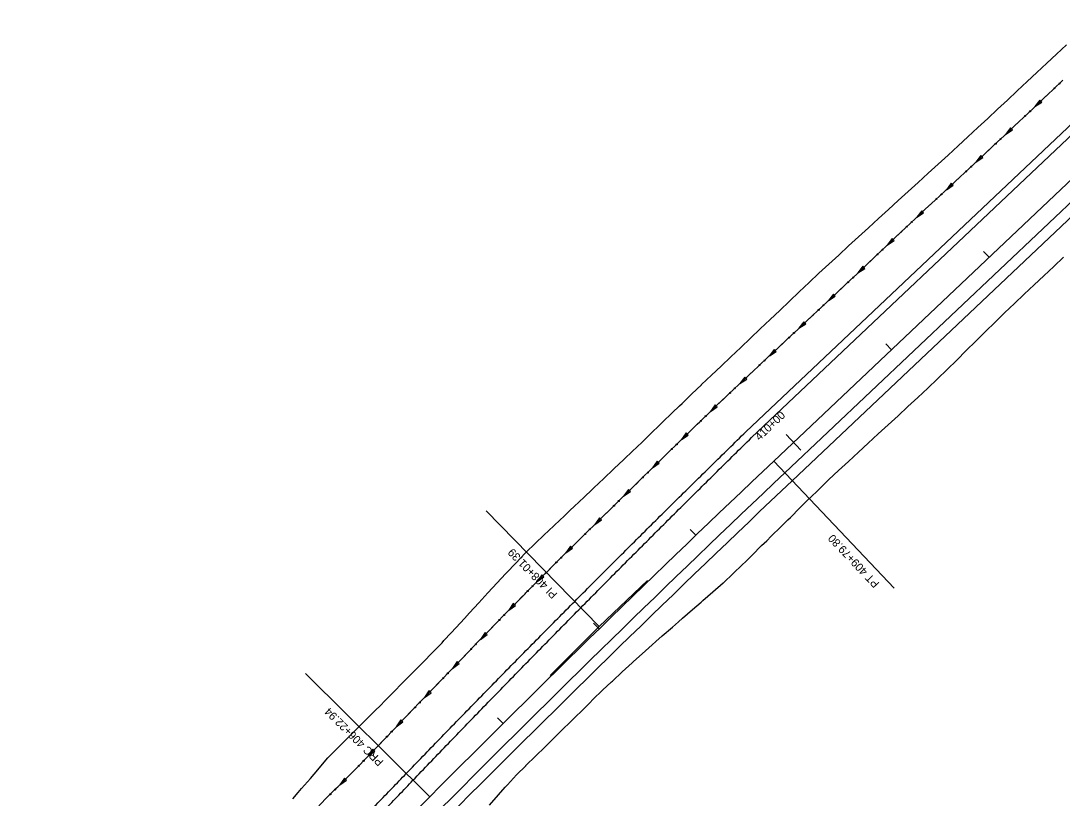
# Model space of a CAD drawing. Extents: x 1375694 to 1433473, y 1931050 to 1967991.
# Drawn here: x 1428720 to 1429493, y 1963792 to 1964369 of the extents above; entities that cross this region are included whole.
import ezdxf

# ---------------------------------------------------------------- set-up
doc = ezdxf.new("R2010")
doc.units = 0
for name, color, linetype in [('62', 7, 'Continuous'), ('R_Horz Alg', 7, 'Continuous'), ('R_Horz Alg Annot', 7, 'Continuous'), ('R_Proposed Const Limits', 7, 'Continuous'), ('R_Proposed Road', 7, 'Continuous')]:
    doc.layers.add(name, color=color, linetype=linetype)

msp = doc.modelspace()

# ---------------------------------------------------------------- linework, layer by layer
at = {"layer": '62'}
for p, q in [((1429476.51, 1964310.5), (1429472.87, 1964305.61)), ((1429472.87, 1964305.61), (1429477.96, 1964308.96)), ((1429477.96, 1964308.96), (1429476.51, 1964310.5)), ((1429454.67, 1964289.88), (1429451.02, 1964285)), ((1429451.02, 1964285), (1429456.11, 1964288.34)), ((1429456.11, 1964288.34), (1429454.67, 1964289.88)), ((1429432.77, 1964269.32), (1429429.12, 1964264.44)), ((1429429.12, 1964264.44), (1429434.22, 1964267.77)), ((1429434.22, 1964267.77), (1429432.77, 1964269.32)), ((1429410.83, 1964248.81), (1429407.15, 1964243.95)), ((1429412.27, 1964247.26), (1429410.83, 1964248.81)), ((1429407.15, 1964243.95), (1429412.27, 1964247.26)), ((1429388.82, 1964228.36), (1429385.15, 1964223.51)), ((1429385.15, 1964223.51), (1429390.26, 1964226.81)), ((1429390.26, 1964226.81), (1429388.82, 1964228.36)), ((1429366.96, 1964207.76), (1429363.33, 1964202.86)), ((1429363.33, 1964202.86), (1429368.41, 1964206.22)), ((1429368.41, 1964206.22), (1429366.96, 1964207.76)), ((1429345.16, 1964187.09), (1429341.53, 1964182.19)), ((1429346.62, 1964185.55), (1429345.16, 1964187.09)), ((1429341.53, 1964182.19), (1429346.62, 1964185.55)), ((1429323.28, 1964166.51), (1429319.63, 1964161.63)), ((1429319.63, 1964161.63), (1429324.73, 1964164.97)), ((1429324.73, 1964164.97), (1429323.28, 1964166.51)), ((1429301.38, 1964145.96), (1429297.72, 1964141.09)), ((1429297.72, 1964141.09), (1429302.82, 1964144.41)), ((1429302.82, 1964144.41), (1429301.38, 1964145.96)), ((1429279.43, 1964125.45), (1429275.77, 1964120.58)), ((1429280.88, 1964123.91), (1429279.43, 1964125.45)), ((1429275.77, 1964120.58), (1429280.88, 1964123.91)), ((1429257.52, 1964104.9), (1429253.87, 1964100.02)), ((1429253.87, 1964100.02), (1429258.97, 1964103.36)), ((1429258.97, 1964103.36), (1429257.52, 1964104.9)), ((1429235.65, 1964084.29), (1429232.08, 1964079.35)), ((1429232.08, 1964079.35), (1429237.12, 1964082.77)), ((1429237.12, 1964082.77), (1429235.65, 1964084.29)), ((1429214.1, 1964063.36), (1429210.54, 1964058.42)), ((1429215.57, 1964061.84), (1429214.1, 1964063.36)), ((1429210.54, 1964058.42), (1429215.57, 1964061.84)), ((1429192.6, 1964042.38), (1429189.04, 1964037.43)), ((1429189.04, 1964037.43), (1429194.08, 1964040.87)), ((1429194.08, 1964040.87), (1429192.6, 1964042.38)), ((1429171.13, 1964021.37), (1429167.59, 1964016.41)), ((1429167.59, 1964016.41), (1429172.61, 1964019.86)), ((1429172.61, 1964019.86), (1429171.13, 1964021.37)), ((1429149.69, 1964000.33), (1429146.15, 1963995.37)), ((1429146.15, 1963995.37), (1429151.17, 1963998.82)), ((1429151.17, 1963998.82), (1429149.69, 1964000.33)), ((1429128.27, 1963979.26), (1429124.75, 1963974.29)), ((1429129.76, 1963977.75), (1429128.27, 1963979.26)), ((1429124.75, 1963974.29), (1429129.76, 1963977.75)), ((1429106.97, 1963958.07), (1429103.48, 1963953.08)), ((1429103.48, 1963953.08), (1429108.47, 1963956.58)), ((1429108.47, 1963956.58), (1429106.97, 1963958.07)), ((1429085.76, 1963936.79), (1429082.34, 1963931.75)), ((1429082.34, 1963931.75), (1429087.28, 1963935.31)), ((1429087.28, 1963935.31), (1429085.76, 1963936.79)), ((1429064.86, 1963915.2), (1429061.46, 1963910.15)), ((1429061.46, 1963910.15), (1429066.39, 1963913.73)), ((1429066.39, 1963913.73), (1429064.86, 1963915.2)), ((1429044, 1963893.6), (1429040.59, 1963888.54)), ((1429045.52, 1963892.13), (1429044, 1963893.6)), ((1429040.59, 1963888.54), (1429045.52, 1963892.13)), ((1429023.16, 1963871.96), (1429019.76, 1963866.9)), ((1429019.76, 1963866.9), (1429024.68, 1963870.49)), ((1429024.68, 1963870.49), (1429023.16, 1963871.96)), ((1429002.32, 1963850.32), (1428998.93, 1963845.26)), ((1428998.93, 1963845.26), (1429003.85, 1963848.85)), ((1429003.85, 1963848.85), (1429002.32, 1963850.32)), ((1428981.52, 1963828.65), (1428978.13, 1963823.58)), ((1428978.13, 1963823.58), (1428983.05, 1963827.19)), ((1428983.05, 1963827.19), (1428981.52, 1963828.65)), ((1428960.55, 1963807.18), (1428957.04, 1963802.2)), ((1428957.04, 1963802.2), (1428962.04, 1963805.69)), ((1428962.04, 1963805.69), (1428960.55, 1963807.18))]:
    msp.add_line(p, q, dxfattribs=at)
for points in [[(1428941.35, 1963786.63), (1428948.44, 1963793.63), (1428954.37, 1963799.54), (1428955.49, 1963800.65), (1428962.54, 1963807.68), (1428969.59, 1963814.7), (1428970.06, 1963815.19), (1428976.49, 1963821.87), (1428983.38, 1963829.06), (1428985.4, 1963831.18), (1428990.32, 1963836.29), (1428997.27, 1963843.54), (1429000.93, 1963847.34), (1429004.24, 1963850.79), (1429011.21, 1963858.02), (1429016.48, 1963863.48), (1429018.19, 1963865.26), (1429025.15, 1963872.51), (1429032.01, 1963879.64), (1429032.12, 1963879.75), (1429039.09, 1963886.99), (1429046.07, 1963894.22), (1429047.57, 1963895.78), (1429053.06, 1963901.44), (1429060.03, 1963908.68), (1429063.15, 1963911.9), (1429067.02, 1963915.91), (1429074, 1963923.14), (1429078.73, 1963928.02), (1429080.99, 1963930.36), (1429088, 1963937.57), (1429094.43, 1963944.03), (1429095.09, 1963944.69), (1429102.2, 1963951.8), (1429109.31, 1963958.91), (1429110.28, 1963959.88), (1429116.42, 1963966), (1429123.55, 1963973.09), (1429126.17, 1963975.7), (1429130.69, 1963980.16), (1429137.85, 1963987.22), (1429142.14, 1963991.43), (1429145.02, 1963994.26), (1429152.19, 1964001.3), (1429158.14, 1964007.13), (1429159.37, 1964008.34), (1429166.54, 1964015.38), (1429173.71, 1964022.42), (1429174.13, 1964022.84), (1429180.89, 1964029.45), (1429188.08, 1964036.49), (1429190.16, 1964038.52), (1429195.27, 1964043.51), (1429202.46, 1964050.53), (1429206.19, 1964054.18), (1429209.65, 1964057.55), (1429216.85, 1964064.57), (1429222.26, 1964069.82), (1429224.06, 1964071.57), (1429231.28, 1964078.57), (1429238.35, 1964085.43), (1429238.49, 1964085.56), (1429245.78, 1964092.41), (1429253.07, 1964099.26), (1429260.35, 1964106.11), (1429267.64, 1964112.96), (1429274.94, 1964119.8), (1429282.24, 1964126.63), (1429289.55, 1964133.46), (1429296.85, 1964140.28), (1429304.16, 1964147.11), (1429311.46, 1964153.95), (1429318.75, 1964160.8), (1429326.04, 1964167.64), (1429333.33, 1964174.49), (1429340.62, 1964181.33), (1429347.88, 1964188.2), (1429355.14, 1964195.09), (1429362.39, 1964201.97), (1429369.65, 1964208.85), (1429376.91, 1964215.73), (1429384.17, 1964222.6), (1429391.5, 1964229.41), (1429398.83, 1964236.21), (1429406.15, 1964243.02), (1429413.48, 1964249.83), (1429420.8, 1964256.63), (1429428.1, 1964263.47), (1429435.39, 1964270.32), (1429442.68, 1964277.17), (1429449.96, 1964284.01), (1429457.25, 1964290.86), (1429464.53, 1964297.72), (1429471.79, 1964304.59), (1429479.06, 1964311.46), (1429486.33, 1964318.33), (1429493.6, 1964325.19)], [(1429483.78, 1964315.91), (1429479.06, 1964311.46), (1429472.87, 1964305.61)], [(1429483.8, 1964315.93), (1429483.78, 1964315.91)], [(1429461.94, 1964295.28), (1429457.25, 1964290.86), (1429451.02, 1964285)], [(1429461.97, 1964295.31), (1429461.94, 1964295.28)], [(1429440.06, 1964274.71), (1429435.39, 1964270.32), (1429429.12, 1964264.44)], [(1429440.08, 1964274.73), (1429440.06, 1964274.71)], [(1429418.14, 1964254.16), (1429413.48, 1964249.83), (1429407.15, 1964243.95)], [(1429418.17, 1964254.19), (1429418.14, 1964254.16)], [(1429396.14, 1964233.72), (1429391.5, 1964229.41), (1429385.15, 1964223.51)], [(1429396.17, 1964233.74), (1429396.14, 1964233.72)], [(1429374.22, 1964213.18), (1429369.65, 1964208.85), (1429363.33, 1964202.86)], [(1429374.24, 1964213.2), (1429374.22, 1964213.18)], [(1429352.42, 1964192.51), (1429347.88, 1964188.2), (1429341.53, 1964182.19)], [(1429352.45, 1964192.53), (1429352.42, 1964192.51)], [(1429330.57, 1964171.9), (1429326.04, 1964167.64), (1429319.63, 1964161.63)], [(1429330.6, 1964171.92), (1429330.57, 1964171.9)], [(1429308.67, 1964151.34), (1429304.16, 1964147.11), (1429297.72, 1964141.09)], [(1429308.7, 1964151.36), (1429308.67, 1964151.34)], [(1429286.73, 1964130.82), (1429282.24, 1964126.63), (1429275.77, 1964120.58)], [(1429286.76, 1964130.85), (1429286.73, 1964130.82)], [(1429264.8, 1964110.29), (1429260.35, 1964106.11), (1429253.87, 1964100.02)], [(1429264.83, 1964110.32), (1429264.8, 1964110.3)], [(1429242.92, 1964089.72), (1429238.49, 1964085.56), (1429238.35, 1964085.43), (1429232.08, 1964079.35)], [(1429242.94, 1964089.75), (1429242.92, 1964089.72)], [(1429221.29, 1964068.88), (1429216.85, 1964064.57), (1429210.54, 1964058.42)], [(1429221.31, 1964068.9), (1429221.29, 1964068.88)], [(1429199.77, 1964047.91), (1429195.27, 1964043.51), (1429190.16, 1964038.52), (1429189.04, 1964037.43)], [(1429199.8, 1964047.94), (1429199.78, 1964047.91)], [(1429178.3, 1964026.91), (1429174.13, 1964022.84), (1429173.71, 1964022.42), (1429167.59, 1964016.41)], [(1429178.32, 1964026.94), (1429178.3, 1964026.91)], [(1429156.86, 1964005.88), (1429152.19, 1964001.3), (1429146.15, 1963995.37)], [(1429156.88, 1964005.9), (1429156.86, 1964005.88)], [(1429135.43, 1963984.83), (1429130.69, 1963980.16), (1429126.17, 1963975.7), (1429124.75, 1963974.29)], [(1429135.45, 1963984.85), (1429135.43, 1963984.83)], [(1429114.09, 1963963.68), (1429110.28, 1963959.88), (1429109.31, 1963958.91), (1429103.48, 1963953.08)], [(1429114.12, 1963963.71), (1429114.09, 1963963.68)], [(1429092.85, 1963942.44), (1429088, 1963937.57), (1429082.34, 1963931.75)], [(1429092.88, 1963942.47), (1429092.85, 1963942.44)], [(1429071.88, 1963920.94), (1429067.02, 1963915.91), (1429063.15, 1963911.9), (1429061.46, 1963910.15)], [(1429071.9, 1963920.97), (1429071.88, 1963920.94)], [(1429051.01, 1963899.33), (1429047.57, 1963895.78), (1429046.07, 1963894.22), (1429040.59, 1963888.54)], [(1429051.04, 1963899.36), (1429051.02, 1963899.33)], [(1429030.18, 1963877.74), (1429030.16, 1963877.71)], [(1429030.16, 1963877.71), (1429025.15, 1963872.51), (1429019.76, 1963866.9)], [(1429009.33, 1963856.07), (1429004.24, 1963850.79), (1429000.93, 1963847.34), (1428998.93, 1963845.26)], [(1429009.36, 1963856.1), (1429009.33, 1963856.07)], [(1428988.51, 1963834.41), (1428985.4, 1963831.18), (1428983.38, 1963829.06), (1428978.13, 1963823.58)], [(1428988.54, 1963834.44), (1428988.51, 1963834.41)], [(1428967.67, 1963812.79), (1428962.54, 1963807.68), (1428957.04, 1963802.2)], [(1428967.69, 1963812.82), (1428967.67, 1963812.79)]]:
    msp.add_lwpolyline(points, dxfattribs=at)
for centre in [(1429487.45, 1964319.33), (1429491.09, 1964322.77), (1429465.62, 1964298.7), (1429469.26, 1964302.15), (1429447.39, 1964281.55), (1429443.74, 1964278.12), (1429421.84, 1964257.56), (1429425.5, 1964260.99), (1429399.84, 1964237.11), (1429403.51, 1964240.52), (1429381.53, 1964220.05), (1429377.89, 1964216.61), (1429356.09, 1964195.94), (1429359.72, 1964199.39), (1429334.26, 1964175.31), (1429337.91, 1964178.74), (1429316.01, 1964158.18), (1429312.36, 1964154.75), (1429290.42, 1964134.23), (1429294.08, 1964137.65), (1429272.14, 1964117.13), (1429268.49, 1964113.71), (1429250.25, 1964096.57), (1429246.6, 1964093.13), (1429224.91, 1964072.35), (1429228.51, 1964075.84), (1429203.39, 1964051.4), (1429206.98, 1964054.9), (1429185.49, 1964033.91), (1429181.91, 1964030.4), (1429160.47, 1964009.37), (1429164.04, 1964012.87), (1429139.03, 1963988.33), (1429142.6, 1963991.84), (1429121.23, 1963970.73), (1429117.68, 1963967.2), (1429099.97, 1963949.52), (1429096.42, 1963945.97), (1429075.4, 1963924.52), (1429078.88, 1963928.13), (1429054.53, 1963902.92), (1429058.01, 1963906.53), (1429033.67, 1963881.31), (1429037.14, 1963884.92), (1429016.32, 1963863.26), (1429012.84, 1963859.66), (1428995.49, 1963841.63), (1428992.02, 1963838.01), (1428971.21, 1963816.34), (1428974.69, 1963819.95), (1428949.97, 1963795.11), (1428953.52, 1963798.64)]:
    msp.add_circle(centre, 0.375, dxfattribs=at)
at = {"layer": 'R_Horz Alg'}
msp.add_line((1429279.02, 1964042.46), (1430431.75, 1965133.47), dxfattribs=at)
for centre, start, end in [((1437156.01, 1955719.88), 133.424411, 135.208721), ((1420891.39, 1971866.43), 313.094012, 315.208721)]:
    msp.add_arc(centre, 11459.16, start, end, dxfattribs=at)
at = {"layer": 'R_Horz Alg Annot'}
for q in [(1429185.43, 1963953.88), (1429113.11, 1963883.21)]:
    msp.add_line((1429149.42, 1963919.79), q, dxfattribs=at)
for points in [[(1429434.82, 1964198.18), (1429438.95, 1964193.82)], [(1429362.2, 1964129.44), (1429366.32, 1964125.08)], [(1429288.19, 1964062.15), (1429299.19, 1964050.53)], [(1429279.02, 1964042.46), (1429368.39, 1963948.04)], [(1429149.42, 1963919.79), (1429065.59, 1964005.65)], [(1429217.1, 1963991.73), (1429221.26, 1963987.4)], [(1429145.22, 1963922.13), (1429149.41, 1963917.84)], [(1429023.7, 1963793.16), (1428931.45, 1963884.74)], [(1429073.95, 1963851.91), (1429078.18, 1963847.66)]]:
    msp.add_lwpolyline(points, dxfattribs=at)
at = {"layer": 'R_Proposed Const Limits'}
for points in [[(1428922.14, 1963791.83), (1428926.19, 1963796.45), (1428928.59, 1963799.44), (1428935.22, 1963806.86), (1428940.63, 1963813.29), (1428941.72, 1963814.42), (1428948.1, 1963822.1), (1428955.1, 1963829.14), (1428955.58, 1963829.62), (1428962.12, 1963836.17), (1428969.17, 1963843.17), (1428971.21, 1963845.27), (1428976.25, 1963850.27), (1428983.32, 1963857.44), (1428987.08, 1963861.14), (1428990.43, 1963864.56), (1428997.56, 1963871.66), (1429002.86, 1963877.11), (1429004.62, 1963878.84), (1429011.67, 1963886.02), (1429018.66, 1963893.06), (1429018.76, 1963893.16), (1429025.83, 1963900.33), (1429032.84, 1963907.56), (1429034.29, 1963909.18), (1429039.61, 1963915.02), (1429046.46, 1963922.41), (1429049.5, 1963925.72), (1429053.24, 1963929.87), (1429060.08, 1963937.27), (1429064.71, 1963942.28), (1429066.9, 1963944.7), (1429073.72, 1963952.12), (1429080.01, 1963958.74), (1429080.65, 1963959.43), (1429087.54, 1963966.78), (1429094.49, 1963974.07), (1429095.49, 1963975.03), (1429101.78, 1963981.02), (1429108.99, 1963988.05), (1429111.71, 1963990.57), (1429116.38, 1963994.89), (1429123.63, 1964001.88), (1429127.99, 1964006.03), (1429130.97, 1964008.77), (1429138.3, 1964015.67), (1429144.31, 1964021.46), (1429145.57, 1964022.64), (1429152.99, 1964029.45), (1429160.22, 1964036.45), (1429160.65, 1964036.86), (1429167.56, 1964043.34), (1429174.79, 1964050.36), (1429176.88, 1964052.38), (1429182.02, 1964057.36), (1429189.24, 1964064.37), (1429193, 1964068.01), (1429196.48, 1964071.38), (1429203.72, 1964078.37), (1429209.15, 1964083.62), (1429210.96, 1964085.36), (1429218.22, 1964092.35), (1429225.33, 1964099.19), (1429225.47, 1964099.32), (1429232.78, 1964106.15), (1429240.09, 1964112.97), (1429247.31, 1964119.89), (1429254.57, 1964126.77), (1429261.77, 1964133.71), (1429269.03, 1964140.59), (1429276.27, 1964147.48), (1429283.51, 1964154.39), (1429290.78, 1964161.25), (1429298.02, 1964168.15), (1429305.27, 1964175.04), (1429312.47, 1964181.98), (1429319.84, 1964188.74), (1429327.25, 1964195.46), (1429334.62, 1964202.22), (1429341.97, 1964209), (1429349.35, 1964215.75), (1429356.72, 1964222.51), (1429364.09, 1964229.27), (1429371.44, 1964236.05), (1429378.88, 1964242.73), (1429386.31, 1964249.43), (1429393.73, 1964256.14), (1429401.18, 1964262.82), (1429408.56, 1964269.57), (1429415.86, 1964276.41), (1429423.18, 1964283.21), (1429430.48, 1964290.05), (1429437.83, 1964296.83), (1429445.16, 1964303.63), (1429452.46, 1964310.48), (1429459.77, 1964317.3), (1429467.03, 1964324.18), (1429474.29, 1964331.05), (1429481.68, 1964337.79), (1429488.97, 1964344.64), (1429496.33, 1964351.4)], [(1429088.05, 1963809.44), (1429095.03, 1963816.35), (1429095.13, 1963816.45), (1429102.25, 1963823.43), (1429109.36, 1963830.43), (1429110.9, 1963831.92), (1429116.47, 1963837.42), (1429123.59, 1963844.4), (1429126.74, 1963847.54), (1429130.69, 1963851.39), (1429137.78, 1963858.4), (1429142.6, 1963863.12), (1429144.87, 1963865.41), (1429152.03, 1963872.36), (1429158.6, 1963878.56), (1429159.28, 1963879.19), (1429166.56, 1963886.02), (1429173.99, 1963892.68), (1429175, 1963893.6), (1429181.37, 1963899.38), (1429188.81, 1963906.04), (1429191.55, 1963908.47), (1429196.3, 1963912.63), (1429203.82, 1963919.19), (1429208.27, 1963923.17), (1429211.3, 1963925.8), (1429218.81, 1963932.37), (1429225.1, 1963937.74), (1429226.38, 1963938.88), (1429233.93, 1963945.41), (1429241.43, 1963951.99), (1429241.87, 1963952.37), (1429248.73, 1963958.77), (1429255.9, 1963965.69), (1429257.97, 1963967.7), (1429262.99, 1963972.7), (1429270.07, 1963979.71), (1429273.8, 1963983.31), (1429277.21, 1963986.67), (1429284.25, 1963993.72), (1429289.6, 1963998.95), (1429291.39, 1964000.68), (1429298.46, 1964007.71), (1429305.39, 1964014.6), (1429305.53, 1964014.73), (1429312.69, 1964021.72), (1429319.84, 1964028.72), (1429327.2, 1964035.49), (1429334.56, 1964042.26), (1429341.88, 1964049.07), (1429349.22, 1964055.86), (1429356.58, 1964062.63), (1429363.98, 1964069.36), (1429371.34, 1964076.13), (1429378.65, 1964082.95), (1429385.94, 1964089.8), (1429393.3, 1964096.57), (1429400.48, 1964103.54), (1429407.68, 1964110.48), (1429414.81, 1964117.5), (1429421.89, 1964124.56), (1429429.01, 1964131.59), (1429436.13, 1964138.6), (1429443.24, 1964145.64), (1429450.38, 1964152.64), (1429457.67, 1964159.49), (1429464.93, 1964166.37), (1429472.19, 1964173.25), (1429479.5, 1964180.07), (1429486.79, 1964186.92), (1429494.02, 1964193.82)], [(1429068.03, 1963787.16), (1429074.7, 1963794.59), (1429079.64, 1963800.29), (1429081.32, 1963802.06), (1429088.05, 1963809.44)]]:
    msp.add_lwpolyline(points, dxfattribs=at)
at = {"layer": 'R_Proposed Road'}
for p, q in [((1429258.4, 1964064.25), (1430411.13, 1965155.26)), ((1429262.53, 1964059.89), (1430415.26, 1965150.9)), ((1429287.27, 1964033.74), (1430440, 1965124.75)), ((1429292.77, 1964027.93), (1430445.5, 1965118.94))]:
    msp.add_line(p, q, dxfattribs=at)
for radius in [11447.16, 11439.16]:
    msp.add_arc((1437156.01, 1955719.88), radius, 133.424411, 135.208721, dxfattribs=at)
for points in [[(1429006.25, 1963810.48), (1429010.39, 1963814.77), (1429018.66, 1963823.36), (1429031.1, 1963836.21), (1429043.56, 1963849.04), (1429056.03, 1963861.85), (1429068.53, 1963874.65), (1429081.05, 1963887.42), (1429093.59, 1963900.18), (1429106.14, 1963912.92), (1429118.72, 1963925.64), (1429131.32, 1963938.33), (1429143.94, 1963951.01), (1429156.58, 1963963.67), (1429169.24, 1963976.31), (1429181.91, 1963988.93), (1429194.61, 1964001.53), (1429207.33, 1964014.12), (1429220.07, 1964026.68), (1429232.83, 1964039.22), (1429245.6, 1964051.75), (1429254.14, 1964060.08), (1429258.4, 1964064.25)], [(1429011.28, 1963805.49), (1429015.4, 1963809.79), (1429023.64, 1963818.4), (1429036.03, 1963831.28), (1429048.44, 1963844.14), (1429060.88, 1963856.99), (1429073.33, 1963869.81), (1429085.8, 1963882.62), (1429098.29, 1963895.41), (1429110.8, 1963908.17), (1429123.34, 1963920.92), (1429135.89, 1963933.65), (1429148.46, 1963946.36), (1429161.06, 1963959.06), (1429173.67, 1963971.73), (1429186.3, 1963984.38), (1429198.96, 1963997.01), (1429211.63, 1964009.63), (1429224.32, 1964022.22), (1429237.04, 1964034.8), (1429249.77, 1964047.36), (1429258.27, 1964055.71), (1429262.53, 1964059.89)], [(1428793.5, 1963595.33), (1428797.09, 1963598.87), (1428804.27, 1963605.96), (1428815.03, 1963616.6), (1428825.78, 1963627.25), (1428836.51, 1963637.92), (1428847.23, 1963648.6), (1428857.93, 1963659.29), (1428868.62, 1963670), (1428879.29, 1963680.72), (1428889.95, 1963691.46), (1428900.6, 1963702.21), (1428911.23, 1963712.98), (1428921.84, 1963723.76), (1428932.45, 1963734.55), (1428943.03, 1963745.35), (1428953.61, 1963756.17), (1428964.17, 1963767.01), (1428974.71, 1963777.85), (1428985.24, 1963788.72), (1428995.75, 1963799.59), (1429002.75, 1963806.85), (1429006.25, 1963810.48)], [(1428799.02, 1963589.55), (1428802.61, 1963593.1), (1428809.78, 1963600.21), (1428820.51, 1963610.89), (1428831.23, 1963621.58), (1428841.94, 1963632.29), (1428852.63, 1963643.01), (1428863.31, 1963653.75), (1428873.97, 1963664.5), (1428884.62, 1963675.26), (1428895.26, 1963686.04), (1428905.88, 1963696.83), (1428916.48, 1963707.63), (1428927.08, 1963718.45), (1428937.65, 1963729.28), (1428948.21, 1963740.13), (1428958.76, 1963750.99), (1428969.29, 1963761.86), (1428979.81, 1963772.75), (1428990.32, 1963783.65), (1429000.8, 1963794.56), (1429007.79, 1963801.85), (1429011.28, 1963805.49)]]:
    msp.add_open_spline(points, degree=3, dxfattribs=at)

# ---------------------------------------------------------------- texts
at = {"layer": 'R_Horz Alg'}
for rotation, p in [(43.42441, (1429279.06, 1964041.8)), (45.20872, (1429023.76, 1963792.5))]:
    msp.add_text('+', height=1, rotation=rotation, dxfattribs=at).set_placement(p)
at = {"layer": 'R_Horz Alg Annot'}
for s, rotation, p in [('410+00', 43.42441, (1429268.5, 1964057.28)), ('PT 409+79.80', 133.42441, (1429357.88, 1963951.87)), ('PI 408+01.39', 134.31657, (1429118.9, 1963943.9)), ('PRC 406+22.94', 135.20872, (1428989.93, 1963819.64))]:
    msp.add_text(s, height=6, rotation=rotation, dxfattribs=at).set_placement(p)

doc.saveas('drawing.dxf')
